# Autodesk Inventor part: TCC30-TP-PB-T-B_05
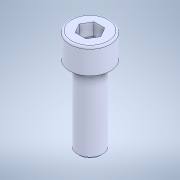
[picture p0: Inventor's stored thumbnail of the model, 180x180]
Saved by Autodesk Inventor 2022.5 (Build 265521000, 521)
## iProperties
Created: 2023-09
Part Number: TCC30-TP-PB-T-B_05
Material: 一般
Document SubType Name: Modeling
Designer: ImaoCorp
Density: 1 g/cm^3
Appearance: 既定
Author: ImaoCorp
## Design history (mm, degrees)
feature "TCC30-TP-PB-T-B_05"
node "ソリッド1"
